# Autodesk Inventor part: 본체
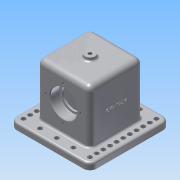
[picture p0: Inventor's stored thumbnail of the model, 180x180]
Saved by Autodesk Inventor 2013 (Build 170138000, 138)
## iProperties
Created: 2018-11
Part Number: 본체
Material: 알루미늄 6061
Document SubType Name: Modeling
Designer: kg
Density: 2.71 g/cm^3
Mass: 1020.7 g
Surface Area: 776.599 cm^2
Volume: 376.644 cm^3
Author: kg
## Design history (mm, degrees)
sketch "스케치1"
  geometry: L1 (-40, -40)-(40, -40); L2 (40, -40)-(40, 40); L3 (40, 40)-(-40, 40); L4 (-40, 40)-(-40, -40); 3 further points
  constraints: 8 end point, 2 midpoint, 2 parallel, 2 perpendicular, 1 horizontal, 1 horizontal alignment, 1 vertical alignment
  dimensions: "d0" = 80 distance of L2.end L3.end
extrude "돌출1" new body sketch "스케치1" distance "d2" = 80; taper "d3" = 0 deg
node "작업 평면1"
sketch "스케치2"
  geometry: L1 (-20, -20)-(100, -20); L2 (100, -20)-(100, 100); L3 (100, 100)-(-20, 100); L4 (-20, 100)-(-20, -20); L5 (0, 80)-(80, 80) reference; L6 (0, 0)-(80, 0) reference; L7 (80, 0)-(80, 80) reference; L8 (0, 80)-(80, 80) reference; L9 (0, 0)-(0, 80) reference; 4 further points
  constraints: 8 end point, 3 midpoint, 2 parallel, 2 perpendicular, 1 horizontal, 1 horizontal alignment, 1 vertical alignment
  dimensions: "d5" = 120 distance of L2.end L3.end
extrude "돌출2" join sketch "스케치2" stored distance "d7" = 10; taper "d8" = 0 deg
node "작업 평면2"
sketch "스케치3"
  geometry: L1 (80, 0)-(0, 0) reference; L2 (80, 0)-(80, 80) reference; C1 r 7.5 at (40, 40); 3 further points
  constraints: 2 midpoint, 1 centre point, 1 horizontal alignment, 1 vertical alignment
  dimensions: "d10" = 15 diameter of C1
extrude "돌출3" join sketch "스케치3" stored distance "d11" = 80; taper "d12" = 0 deg
sketch "스케치5"
  geometry: L1 (120, -120)-(120, 0) reference; L2 (120, 0)-(0, 0) reference; L3 (0, 0)-(0, -120) reference; L4 (0, -120)-(120, -120) reference; L5 (100, -20)-(100, -100) reference; L6 (20, -100)-(100, -100) reference; L7 (20, -20)-(20, -100) reference; L8 (20, -20)-(100, -20) reference; 1 further point
sketch "스케치7"
  geometry: L1 (100, -20)-(100, 100) reference; L2 (17, 10)-(63, 10); L3 (63, 10)-(63, 70); L4 (63, 70)-(17, 70); L5 (17, 70)-(17, 10); 4 further points
  constraints: 8 end point, 3 midpoint, 2 parallel, 1 horizontal, 1 horizontal alignment, 1 perpendicular, 1 vertical alignment
  dimensions: "d20" = 46 distance of L2.start L2.end; "d22" = 60 distance of L2.end L3.end
extrude "돌출5" cut sketch "스케치7" distance "d23" = 80; taper "d24" = 0 deg
sketch "스케치8"
  geometry: L1 (80, 0)-(80, -80) reference; L2 (0, 0)-(80, 0) reference; C1 r 16.5 at (40, -40); 3 further points
  constraints: 2 midpoint, 1 centre point, 1 horizontal alignment, 1 vertical alignment
  dimensions: "d25" = 33 diameter of C1
extrude "돌출6" cut sketch "스케치8" distance "d26" = 80; taper "d27" = 0 deg
sketch "스케치9"
  geometry: C1 r 16.5 at (40, -40) reference; C2 r 20 at (40, -40); 1 further point
  constraints: 1 centre point, 1 coincident
  dimensions: "d28" = 40 diameter of C2
extrude "돌출7" cut sketch "스케치9" distance "d29" = 14; taper "d30" = 0 deg
node "작업 평면3"
sketch "스케치10"
  geometry: C1 r 7.5 at (0, 0) reference; 1 further point
sketch "스케치11"
  geometry: C1 r 7.5 at (0, 0) reference; 2 further points
  constraints: 1 coincident
hole "구멍1" sketch "스케치11" at (0, 0) diameter "d31" = 4.917; stored, may be unused: countersink angle "d35" = 90 deg, drill point angle "d37" = 118 deg; dims "d32" = 6, "d33" = 4, "d34" = 2, "d36" = 8
sketch "스케치12"
  geometry: L1 (120, -120)-(120, 0) reference; L2 (0, 0)-(0, -120) reference; L3 (0, -60)-(120, -60); C1 r 3.3 at (10, -10); C2 r 3.3 at (20, -10); C3 r 3.3 at (30, -10); C4 r 3.3 at (40, -10); C5 r 3.3 at (50, -10); C6 r 3.3 at (60, -10); 2 further points
  constraints: 6 centre point, 5 equal radius, 5 horizontal alignment, 3 midpoint, 2 end point, 1 vertical alignment
  dimensions: "d38" = 6.6 diameter of C1; "d40" = 100 diameter of C1.centre L3; "d41" = 10 distance of C2.centre C1.centre; "d42" = 10 distance of C3.centre C2.centre; "d43" = 10 distance of C4.centre C3.centre; "d44" = 10 distance of C5.centre C4.centre; "d45" = 10 distance of C6.centre C5.centre
extrude "돌출8" cut sketch "스케치12" distance "d46" = 14; taper "d47" = 0 deg
sketch "스케치13"
  geometry: L1 (0, -120)-(120, -120) reference; C1 r 3.3 at (10, -10) reference; C2 r 2.458 at (60, -60) reference; C3 r 3.3 at (10, -110); C4 r 3.3 at (10, -85); C5 r 3.3 at (10, -60); C6 r 3.3 at (10, -35); 1 further point
  constraints: 4 centre point, 4 vertical alignment, 3 equal radius
  dimensions: "d56" = 6.6 diameter of C3; "d58" = 25 distance of C1.centre C6.centre; "d59" = 25 distance of C6.centre C5.centre; "d60" = 25 distance of C4.centre C5.centre; "d61" = 10 distance from line of L1 C3.centre
extrude "돌출9" cut sketch "스케치13" distance "d62" = 14; taper "d63" = 0 deg
node "작업 평면4"
sketch "스케치14"
  geometry: C1 r 20 at (40, -40) reference; 5 further points
  constraints: 2 horizontal alignment, 2 vertical alignment
  dimensions: "d64" = 52 distance of point (40, -66) point (40, -14); "d66" = 52 distance of point (66, -40) point (14, -40); "d67" = 26 distance of C1.centre point (40, -14); "d68" = 26 distance of C1.centre point (66, -40)
hole "구멍2" sketch "스케치14" at (40, -14), (66, -40), (40, -66), (14, -40) diameter "d69" = 3.242; stored, may be unused: countersink angle "d73" = 90 deg, drill point angle "d75" = 118 deg; dims "d70" = 8, "d71" = 4, "d72" = 2, "d74" = 10
node "작업 평면5"
sketch "스케치15"
  geometry: L1 (60, -50)-(-60, -50) reference; 2 further points
  constraints: 1 vertical alignment, 1 other
  dimensions: "d77" = 48 distance from line of L1 point (0, -2)
feature "엠보싱1" sketch "스케치15" dims "d5" = 120, "d78" = 0.5, "d79" = 0
fillet "모깎기1" dims "d80" = 0.6
fillet "모깎기2" dims "d81" = 0.6
chamfer "모따기1" distance "d82" = 1; stored, may be unused: second distance "d83" = 2, angle "d84" = 45 deg
fillet "모깎기3" dims "d85" = 3
fillet "모깎기4" dims "d86" = 8
fillet "모깎기5" dims "d87" = 3
fillet "모깎기6" dims "d88" = 3
fillet "모깎기7" dims "d89" = 10
fillet "모깎기8" dims "d90" = 3
node "솔리드1"
mirror "대칭1"
mirror "대칭2"
mirror "대칭3"
mirror "대칭4"
mirror "대칭5"
node "투영된 루프1"
other parameters: "d9" = -95, "d76" = 5
